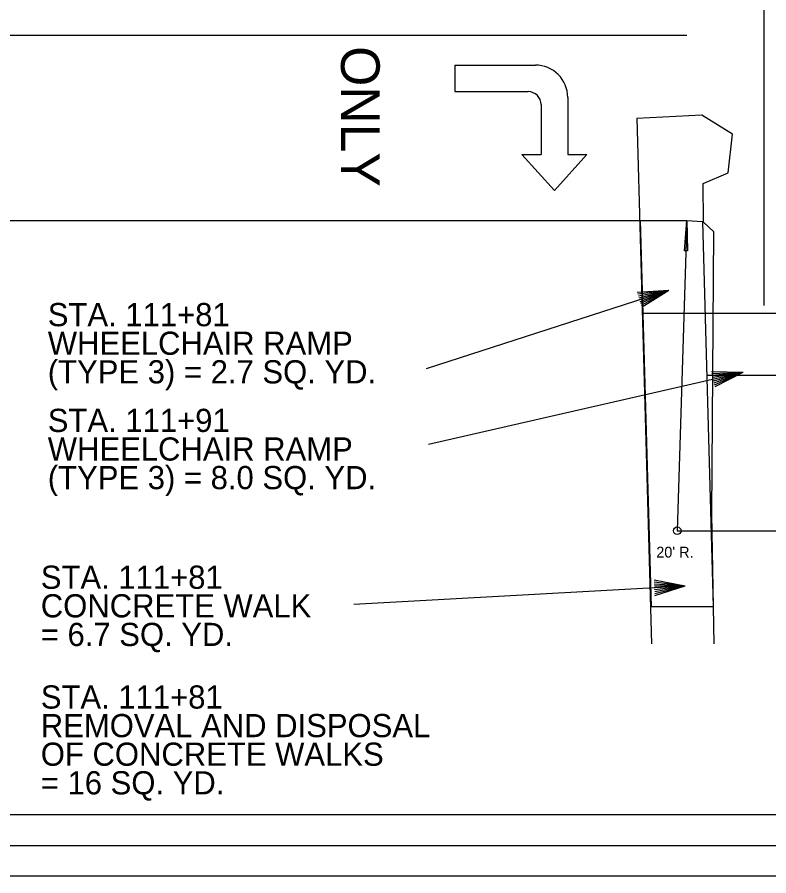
# Model space of a CAD drawing. Extents: x 1944905 to 1956777, y 763871 to 764977.
# Drawn here: x 1948938 to 1949424, y 763871 to 764426 of the extents above; entities that cross this region are included whole.
import ezdxf

# ---------------------------------------------------------------- set-up
doc = ezdxf.new("R2010")
doc.units = 0
for name, color, linetype in [('A_Sidewalk', 7, 'Continuous'), ('Default', 7, 'Continuous'), ('R_Horz Alg', 7, 'Continuous'), ('R_Water', 7, 'Continuous'), ('S_CROSS_DRAIN', 7, 'Continuous')]:
    doc.layers.add(name, color=color, linetype=linetype)

msp = doc.modelspace()

# ---------------------------------------------------------------- linework, layer by layer
at = {"layer": 'A_Sidewalk'}
for p, q in [((1949342.94, 764234.61), (1949507.88, 764234.61)), ((1949384.05, 764194.61), (1949538.21, 764194.61))]:
    msp.add_line(p, q, dxfattribs=at)
msp.add_lwpolyline([(1949341.27, 764294.62), (1949371.21, 764294.62), (1949381.28, 764294.05), (1949388.22, 764044.61), (1949348.2, 764044.61)], close=True, dxfattribs=at)
at = {"layer": 'Default'}
for p, q in [((1949221.21, 764395.17), (1949221.21, 764378)), ((1949221.21, 764395.17), (1949273.17, 764395.17)), ((1949221.21, 764378), (1949268.57, 764378)), ((1949294.13, 764374.21), (1949294.13, 764337.31)), ((1949276.96, 764369.61), (1949276.96, 764337.31)), ((1949264.53, 764337.31), (1949276.96, 764337.31)), ((1949264.53, 764337.31), (1949285.53, 764314.06)), ((1949285.53, 764314.06), (1949306.55, 764337.31)), ((1949294.13, 764337.31), (1949306.55, 764337.31)), ((1949371.21, 764294.62), (1949364.95, 764093.95)), ((1949369.62, 764275.11), (1949371.21, 764294.62)), ((1949371.21, 764294.62), (1949371.58, 764275.05)), ((1949371.58, 764275.05), (1949369.62, 764275.11)), ((1949369.62, 764275.04), (1949369.62, 764275.11)), ((1949202.88, 764198.79), (1949359.48, 764249.64)), ((1949339.09, 764248.28), (1949359.48, 764249.64)), ((1949339.48, 764247.09), (1949359.48, 764249.64)), ((1949339.86, 764245.9), (1949359.48, 764249.64)), ((1949340.25, 764244.71), (1949359.48, 764249.64)), ((1949341.02, 764242.33), (1949359.48, 764249.64)), ((1949341.41, 764241.15), (1949359.48, 764249.64)), ((1949341.79, 764239.96), (1949359.48, 764249.64)), ((1949342.18, 764238.77), (1949359.48, 764249.64)), ((1949204.17, 764149.92), (1949407.58, 764196.49)), ((1949387.14, 764196.94), (1949407.58, 764196.49)), ((1949387.42, 764195.72), (1949407.58, 764196.49)), ((1949387.7, 764194.51), (1949407.58, 764196.49)), ((1949387.98, 764193.29), (1949407.58, 764196.49)), ((1949388.54, 764190.85), (1949407.58, 764196.49)), ((1949388.82, 764189.63), (1949407.58, 764196.49)), ((1949389.1, 764188.41), (1949407.58, 764196.49)), ((1949389.38, 764187.2), (1949407.58, 764196.49)), ((1949364.95, 764093.95), (1949564.95, 764093.95)), ((1949349.97, 764062.11), (1949370.03, 764058.21)), ((1949350.04, 764060.86), (1949370.03, 764058.21)), ((1949350.11, 764059.61), (1949370.03, 764058.21)), ((1949155.86, 764046.34), (1949370.03, 764058.21)), ((1949350.05, 764057.1), (1949370.03, 764058.21)), ((1949350.18, 764058.36), (1949370.03, 764058.21)), ((1949350.32, 764055.87), (1949370.03, 764058.21)), ((1949350.38, 764054.62), (1949370.03, 764058.21)), ((1949350.45, 764053.37), (1949370.03, 764058.21)), ((1949350.52, 764052.12), (1949370.03, 764058.21)), ((1949941.01, 763910.07), (1948360.11, 763910.07)), ((1948327.27, 763890.36), (1949941.01, 763890.36)), ((1948327.27, 763870.67), (1949941.01, 763870.67))]:
    msp.add_line(p, q, dxfattribs=at)
for points in [[(1949381.86, 764293.54), (1949381.68, 764318.65), (1949397.82, 764325.51), (1949400.77, 764350.42), (1949380.78, 764362.74), (1949338.88, 764360.55), (1949348.3, 764020.79)], [(1949388.81, 764020.79), (1949387.3, 764104.59), (1949388.57, 764287.41), (1949381.86, 764293.54)]]:
    msp.add_lwpolyline(points, dxfattribs=at)
msp.add_circle((1949364.95, 764093.95), 2.44, dxfattribs=at)
for centre, radius in [((1949273.18, 764374.21), 20.96), ((1949268.58, 764369.61), 8.38)]:
    msp.add_arc(centre, radius, 360, 90, dxfattribs=at)
at = {"layer": 'R_Horz Alg'}
for p, q in [((1948371.21, 764414.62), (1949371.21, 764414.62)), ((1948371.21, 764294.62), (1949342.78, 764294.62))]:
    msp.add_line(p, q, dxfattribs=at)
at = {"layer": 'R_Water'}
msp.add_line((1949421.26, 764239.61), (1949421.26, 764388.17), dxfattribs=at)
at = {"layer": 'S_CROSS_DRAIN'}
msp.add_line((1949421.26, 764388.17), (1949421.26, 764680.26), dxfattribs=at)

# ---------------------------------------------------------------- texts
at = {"layer": 'Default'}
msp.add_text('ONLY', height=25, rotation=270, dxfattribs=at).set_placement((1949147.49, 764407.44))
for s, height, p in [('STA. 111+81', 15, (1948957.84, 764226.25)), ('WHEELCHAIR RAMP', 15, (1948957.84, 764207.74)), ('(TYPE 3) = 2.7 SQ. YD.', 15, (1948957.84, 764189.24)), ('STA. 111+91', 15, (1948957.84, 764157.82)), ('WHEELCHAIR RAMP', 15, (1948957.84, 764139.31)), ('(TYPE 3) = 8.0 SQ. YD.', 15, (1948957.84, 764120.81)), ("20' R.", 7, (1949351.37, 764076.57)), ('STA. 111+81', 15, (1948953.32, 764056.36)), ('CONCRETE WALK', 15, (1948953.32, 764037.86)), ('= 6.7 SQ. YD.', 15, (1948953.32, 764019.35)), ('STA. 111+81', 15, (1948953.32, 763978.87)), ('REMOVAL AND DISPOSAL', 15, (1948953.32, 763960.37)), ('OF CONCRETE WALKS', 15, (1948953.32, 763941.87)), ('= 16 SQ. YD.', 15, (1948953.32, 763923.37))]:
    msp.add_text(s, height=height, dxfattribs=at).set_placement(p)

doc.saveas('drawing.dxf')
